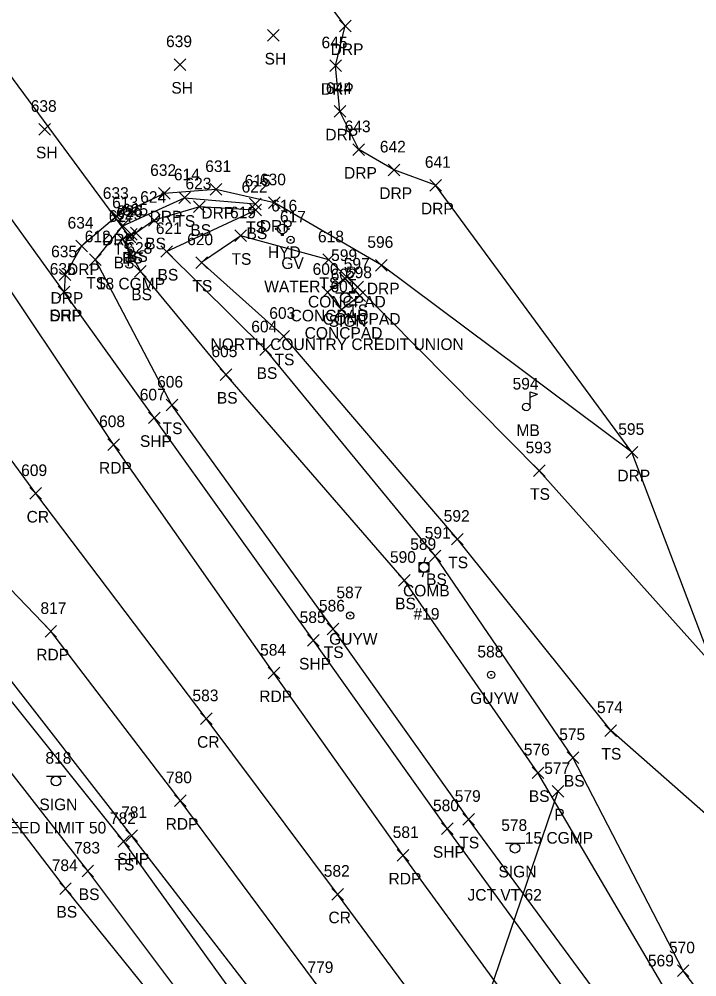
# Model space of a CAD drawing. Extents: x 1623612 to 1625808, y 621345 to 627748.
# Drawn here: x 1625034.6 to 1625151.1, y 625852 to 626016.7 of the extents above; entities that cross this region are included whole.
import ezdxf

# ---------------------------------------------------------------- set-up
doc = ezdxf.new("R2010")
doc.units = 0
for name, color, linetype in [('D_A', 7, 'Continuous'), ('D_C', 7, 'Continuous'), ('D_I', 7, 'Continuous'), ('D_TIC', 7, 'Continuous'), ('DCP', 7, 'Continuous'), ('L_A', 7, 'Continuous'), ('L_I', 7, 'Continuous'), ('L_TIC', 7, 'Continuous'), ('LELB', 7, 'Continuous'), ('LMB', 7, 'Continuous'), ('LS', 7, 'Continuous'), ('LSOGP', 7, 'Continuous'), ('P_A', 7, 'Continuous'), ('P_I', 7, 'Continuous'), ('P_TIC', 7, 'Continuous'), ('PET', 7, 'Continuous'), ('PRC', 7, 'Continuous'), ('PSP', 7, 'Continuous'), ('R_A', 7, 'Continuous'), ('R_I', 7, 'Continuous'), ('R_TIC', 7, 'Continuous'), ('RDP', 7, 'Continuous'), ('S_A', 7, 'Continuous'), ('S_C', 7, 'Continuous'), ('S_I', 7, 'Continuous'), ('SSGN', 7, 'Continuous'), ('U_A', 7, 'Continuous'), ('U_C', 7, 'Continuous'), ('U_I', 7, 'Continuous'), ('UP', 7, 'Continuous'), ('UPGW', 7, 'Continuous'), ('UWFH', 7, 'Continuous'), ('UWV', 7, 'Continuous')]:
    doc.layers.add(name, color=color, linetype=linetype)

msp = doc.modelspace()

# ---------------------------------------------------------------- linework, layer by layer
at = {"layer": 'D_TIC'}
for points in [[(1625052.65, 625978.21), (1625054.65, 625980.21)], [(1625054.65, 625978.21), (1625052.65, 625980.21)], [(1625126.23, 625882.89), (1625128.23, 625884.89)], [(1625128.23, 625882.89), (1625126.23, 625884.89)]]:
    msp.add_lwpolyline(points, dxfattribs=at)
at = {"layer": 'DCP'}
for points in [[(1625053.65, 625979.21), (1625018.74, 626026.52)], [(1625127.23, 625883.89), (1625098.95, 625800.84)]]:
    msp.add_lwpolyline(points, dxfattribs=at)
at = {"layer": 'L_TIC'}
for points in [[(1625077.3, 626012.9), (1625079.3, 626014.9)], [(1625079.3, 626012.9), (1625077.3, 626014.9)], [(1625061.27, 626007.89), (1625063.27, 626009.89)], [(1625063.27, 626007.89), (1625061.27, 626009.89)], [(1625037.99, 625996.76), (1625039.99, 625998.76)], [(1625039.99, 625996.76), (1625037.99, 625998.76)], [(1625062.04, 625984.99), (1625064.04, 625986.99)], [(1625064.04, 625984.99), (1625062.04, 625986.99)], [(1625064.59, 625983.43), (1625066.59, 625985.43)], [(1625066.59, 625983.43), (1625064.59, 625985.43)], [(1625074.2, 625983.93), (1625076.2, 625985.93)], [(1625076.2, 625983.93), (1625074.2, 625985.93)], [(1625074.25, 625982.87), (1625076.25, 625984.87)], [(1625076.25, 625982.87), (1625074.25, 625984.87)], [(1625056.82, 625981.11), (1625058.82, 625983.11)], [(1625058.82, 625981.11), (1625056.82, 625983.11)], [(1625051.42, 625980.17), (1625053.42, 625982.17)], [(1625053.42, 625980.17), (1625051.42, 625982.17)], [(1625051.39, 625977.83), (1625053.39, 625979.83)], [(1625053.39, 625977.83), (1625051.39, 625979.83)], [(1625052.86, 625978.67), (1625054.86, 625980.67)], [(1625054.86, 625978.67), (1625052.86, 625980.67)], [(1625053.71, 625978.94), (1625055.71, 625980.94)], [(1625055.71, 625978.94), (1625053.71, 625980.94)], [(1625071.69, 625978.45), (1625073.69, 625980.45)], [(1625073.69, 625978.45), (1625071.69, 625980.45)], [(1625058.94, 625975.74), (1625060.94, 625977.74)], [(1625060.94, 625975.74), (1625058.94, 625977.74)], [(1625046.71, 625974.33), (1625048.71, 625976.33)], [(1625048.71, 625974.33), (1625046.71, 625976.33)], [(1625064.97, 625973.83), (1625066.97, 625975.83)], [(1625066.97, 625973.83), (1625064.97, 625975.83)], [(1625064.97, 625973.83), (1625066.97, 625975.83)], [(1625066.97, 625973.83), (1625064.97, 625975.83)], [(1625086.81, 625974.31), (1625088.81, 625976.31)], [(1625088.81, 625974.31), (1625086.81, 625976.31)], [(1625054.43, 625972.35), (1625056.43, 625974.35)], [(1625056.43, 625972.35), (1625054.43, 625974.35)], [(1625054.43, 625972.35), (1625056.43, 625974.35)], [(1625056.43, 625972.35), (1625054.43, 625974.35)], [(1625089.6, 625971.11), (1625091.6, 625973.11)], [(1625091.6, 625971.11), (1625089.6, 625973.11)], [(1625091.77, 625969.63), (1625093.77, 625971.63)], [(1625093.77, 625969.63), (1625091.77, 625971.63)], [(1625086.63, 625968.72), (1625088.63, 625970.72)], [(1625088.63, 625968.72), (1625086.63, 625970.72)], [(1625092.15, 625968.15), (1625094.15, 625970.15)], [(1625094.15, 625968.15), (1625092.15, 625970.15)], [(1625092.15, 625968.15), (1625094.15, 625970.15)], [(1625094.15, 625968.15), (1625092.15, 625970.15)], [(1625089.04, 625965.73), (1625091.04, 625967.73)], [(1625091.04, 625965.73), (1625089.04, 625967.73)], [(1625089.04, 625965.73), (1625091.04, 625967.73)], [(1625091.04, 625965.73), (1625089.04, 625967.73)], [(1625079.09, 625961.16), (1625081.09, 625963.16)], [(1625081.09, 625961.16), (1625079.09, 625963.16)], [(1625075.98, 625958.83), (1625077.98, 625960.83)], [(1625077.98, 625958.83), (1625075.98, 625960.83)], [(1625069.14, 625954.57), (1625071.14, 625956.57)], [(1625071.14, 625954.57), (1625069.14, 625956.57)], [(1625059.85, 625949.33), (1625061.85, 625951.33)], [(1625061.85, 625949.33), (1625059.85, 625951.33)], [(1625123.03, 625938.03), (1625125.03, 625940.03)], [(1625125.03, 625938.03), (1625123.03, 625940.03)], [(1625108.95, 625926.26), (1625110.95, 625928.26)], [(1625110.95, 625926.26), (1625108.95, 625928.26)], [(1625105.12, 625923.37), (1625107.12, 625925.37)], [(1625107.12, 625923.37), (1625105.12, 625925.37)], [(1625099.8, 625919.19), (1625101.8, 625921.19)], [(1625101.8, 625919.19), (1625099.8, 625921.19)], [(1625087.56, 625910.82), (1625089.56, 625912.82)], [(1625089.56, 625910.82), (1625087.56, 625912.82)], [(1625135.3, 625893.35), (1625137.3, 625895.35)], [(1625137.3, 625893.35), (1625135.3, 625895.35)], [(1625128.81, 625888.7), (1625130.81, 625890.7)], [(1625130.81, 625888.7), (1625128.81, 625890.7)], [(1625122.78, 625886.07), (1625124.78, 625888.07)], [(1625124.78, 625886.07), (1625122.78, 625888.07)], [(1625110.86, 625878.08), (1625112.86, 625880.08)], [(1625112.86, 625878.08), (1625110.86, 625880.08)], [(1625051.58, 625874.28), (1625053.58, 625876.28)], [(1625053.58, 625874.28), (1625051.58, 625876.28)], [(1625045.4, 625869.19), (1625047.4, 625871.19)], [(1625047.4, 625869.19), (1625045.4, 625871.19)], [(1625041.56, 625866.17), (1625043.56, 625868.17)], [(1625043.56, 625866.17), (1625041.56, 625868.17)], [(1625147.76, 625852.03), (1625149.76, 625854.03)], [(1625149.76, 625852.03), (1625147.76, 625854.03)]]:
    msp.add_lwpolyline(points, dxfattribs=at)
at = {"layer": 'LELB'}
for points in [[(1625193.27, 625769.69), (1625186.11, 625778.21), (1625160.35, 625812.67), (1625137, 625844.95), (1625111.86, 625879.08), (1625088.56, 625911.82), (1625060.85, 625950.33), (1625047.71, 625975.33), (1625052.42, 625981.17), (1625063.04, 625985.99), (1625075.2, 625984.93)], [(1625202.25, 625783.14), (1625192.15, 625794.04), (1625172.86, 625821.27), (1625148.76, 625853.03), (1625129.81, 625889.7), (1625106.12, 625924.37), (1625076.98, 625959.83), (1625059.94, 625976.74), (1625075.25, 625983.87), (1625065.59, 625984.43), (1625057.82, 625982.11), (1625054.71, 625979.94), (1625053.86, 625979.67), (1625052.39, 625978.83), (1625055.43, 625973.35)], [(1625180.7, 625879.29), (1625153.81, 625905.72), (1625124.03, 625939.03), (1625092.77, 625970.63), (1625087.81, 625975.31), (1625072.69, 625979.45), (1625065.97, 625974.83)], [(1625193.27, 625769.69), (1625208.4, 625785.19), (1625203.23, 625794.82), (1625182.56, 625829.07), (1625166.96, 625867.34), (1625136.3, 625894.35), (1625109.95, 625927.26), (1625080.09, 625962.16), (1625065.97, 625974.83)], [(1625202.25, 625783.14), (1625199.96, 625782.54), (1625187.42, 625789.56), (1625167.73, 625817.91), (1625145.11, 625850.78), (1625123.78, 625887.07), (1625100.8, 625920.19), (1625070.14, 625955.57), (1625055.43, 625973.35)], [(1625168.33, 625721.63), (1625149.76, 625746.59), (1625126.59, 625769.43), (1625106.2, 625803.62), (1625076.77, 625841.58), (1625052.58, 625875.28), (1625029.12, 625904.57), (1625004.47, 625931.93), (1624997.4, 625934.09), (1624989.72, 625933.4), (1624984.53, 625931.05), (1624958.97, 625909.04), (1624940.42, 625892.52)], [(1625164.57, 625720.98), (1625144.51, 625741.54), (1625124.06, 625766.95), (1625099.82, 625799.97), (1625096.5, 625807.22), (1625092.35, 625808.68), (1625071.36, 625836.97), (1625046.4, 625870.19), (1625023.79, 625899.18), (1625007.76, 625918.06), (1624995.06, 625928.3), (1624989.75, 625931.76), (1624987.2, 625929.74), (1624981.22, 625924.84), (1624974.29, 625920.07), (1624955.76, 625903.44), (1624945.54, 625893.78)], [(1625164.57, 625720.98), (1625161.19, 625718.67), (1625141.31, 625740.15), (1625121.97, 625765.1), (1625091.91, 625801.43), (1625090.38, 625805.38), (1625068.6, 625834.91), (1625042.56, 625867.17), (1625020.24, 625896.3), (1625004.95, 625914.55), (1624991.81, 625925.45), (1624982.31, 625924.1), (1624975.67, 625918.28), (1624956.23, 625901.03), (1624946.56, 625892.17)]]:
    msp.add_lwpolyline(points, dxfattribs=at)
at = {"layer": 'LMB'}
for p, q in [((1625122.44, 625952.61), (1625123.73, 625952.22)), ((1625122.44, 625950.01), (1625122.44, 625952.61)), ((1625122.44, 625951.71), (1625123.73, 625952.21)), ((1625121.79, 625950), (1625121.79, 625950))]:
    msp.add_line(p, q, dxfattribs=at)
msp.add_circle((1625121.79, 625950), 0.656, dxfattribs=at)
at = {"layer": 'LS'}
for points in [[(1625093.15, 625969.15), (1625090.6, 625972.11), (1625087.63, 625969.72), (1625090.04, 625966.73)], [(1625093.15, 625969.15), (1625090.04, 625966.73)]]:
    msp.add_lwpolyline(points, dxfattribs=at)
at = {"layer": 'LSOGP'}
msp.add_lwpolyline([(1625200.23, 625842.69), (1625180.7, 625879.29), (1625153.81, 625905.72), (1625139.96, 625942.2), (1625106.19, 625988.13), (1625099.02, 625990.77), (1625092.97, 625994.26), (1625089.75, 626000.84), (1625088.99, 626008.69), (1625090.67, 626015.53), (1625069.92, 626043.19), (1625069.59, 626043.56), (1625065.69, 626051.8), (1625058.49, 626067.08), (1625045.18, 626082.05), (1625027.59, 626097.53), (1625025.64, 626131.89)], dxfattribs=at)
at = {"layer": 'P_TIC'}
for points in [[(1625041.32, 625968.75), (1625043.32, 625970.75)], [(1625043.32, 625968.75), (1625041.32, 625970.75)], [(1625056.82, 625947.13), (1625058.82, 625949.13)], [(1625058.82, 625947.13), (1625056.82, 625949.13)], [(1625049.83, 625942.53), (1625051.83, 625944.53)], [(1625051.83, 625942.53), (1625049.83, 625944.53)], [(1625036.44, 625934.12), (1625038.44, 625936.12)], [(1625038.44, 625934.12), (1625036.44, 625936.12)], [(1625039.04, 625910.41), (1625041.04, 625912.41)], [(1625041.04, 625910.41), (1625039.04, 625912.41)], [(1625084.19, 625908.84), (1625086.19, 625910.84)], [(1625086.19, 625908.84), (1625084.19, 625910.84)], [(1625077.39, 625903.23), (1625079.39, 625905.23)], [(1625079.39, 625903.23), (1625077.39, 625905.23)], [(1625065.75, 625895.39), (1625067.75, 625897.39)], [(1625067.75, 625895.39), (1625065.75, 625897.39)], [(1625061.28, 625881.29), (1625063.28, 625883.29)], [(1625063.28, 625881.29), (1625061.28, 625883.29)], [(1625107.2, 625876.47), (1625109.2, 625878.47)], [(1625109.2, 625876.47), (1625107.2, 625878.47)], [(1625052.93, 625875.29), (1625054.93, 625877.29)], [(1625054.93, 625875.29), (1625052.93, 625877.29)], [(1625099.61, 625871.87), (1625101.61, 625873.87)], [(1625101.61, 625871.87), (1625099.61, 625873.87)], [(1625088.34, 625865.2), (1625090.34, 625867.2)], [(1625090.34, 625865.2), (1625088.34, 625867.2)]]:
    msp.add_lwpolyline(points, dxfattribs=at)
at = {"layer": 'PET'}
for points in [[(1625223.77, 625705.98), (1625197.34, 625741.92), (1625177.42, 625768.95), (1625149.4, 625806.39), (1625126.15, 625837.91), (1625100.61, 625872.87), (1625078.39, 625904.23), (1625050.83, 625943.53), (1625026.61, 625979.68), (1625001.56, 626017.54), (1624975.55, 626056.33), (1624956.14, 626085.5), (1624926, 626129.47), (1624907.51, 626155.92), (1624881.56, 626192.36), (1624859.36, 626223.09), (1624835.81, 626254.93), (1624815.05, 626283.37), (1624795.69, 626312.41), (1624789.97, 626324.03), (1624786.26, 626337.17), (1624785.07, 626353.04), (1624787.66, 626371.25), (1624792.4, 626386.87)], [(1625203.84, 625692.06), (1625178.56, 625725.93), (1625159.1, 625752.13), (1625138.75, 625779.51), (1625115.85, 625810.21), (1625086.53, 625849.64), (1625062.28, 625882.29), (1625040.04, 625911.41), (1625011.87, 625940.67), (1624992.38, 625961.15), (1624963.94, 625995.04), (1624945.44, 626018.77), (1624918.36, 626053.4), (1624893.3, 626084.98), (1624858.44, 626129.32)]]:
    msp.add_lwpolyline(points, dxfattribs=at)
at = {"layer": 'PRC'}
msp.add_lwpolyline([(1625213.58, 625698.73), (1625187.25, 625734.61), (1625167.02, 625761.6), (1625139.37, 625799.19), (1625115.73, 625830.47), (1625089.34, 625866.2), (1625066.75, 625896.39), (1625037.44, 625935.12), (1625012.58, 625969.02), (1624983.87, 626006.31), (1624957.44, 626043.36), (1624936.34, 626072.24), (1624905.82, 626116.16), (1624884.45, 626141.57), (1624859.03, 626175.57)], dxfattribs=at)
at = {"layer": 'PSP'}
for points in [[(1625197.89, 625687.83), (1625193.57, 625693.81), (1625173.65, 625722.07), (1625153.52, 625749.21), (1625132.81, 625774.23), (1625108.64, 625805.39), (1625079.11, 625843.61), (1625053.93, 625876.29), (1625030.83, 625905.94), (1625006.8, 625934.64), (1624989.43, 625958.35), (1624960.91, 625992.11), (1624942.41, 626016.35), (1624915.38, 626050.56), (1624890.43, 626082.85), (1624855.5, 626126.62)], [(1625229.23, 625710.23), (1625203.41, 625745.51), (1625190.36, 625762.87), (1625182.48, 625773.25), (1625155.83, 625810.32), (1625133.5, 625842.77), (1625108.2, 625877.47), (1625085.19, 625909.84), (1625057.82, 625948.13), (1625042.32, 625969.75), (1625027.64, 625990.04), (1625006.51, 626020.44), (1624979.39, 626058.85), (1624958.59, 626087.14), (1624930.55, 626127.2)]]:
    msp.add_lwpolyline(points, dxfattribs=at)
at = {"layer": 'R_TIC'}
for points in [[(1625089.67, 626014.53), (1625091.67, 626016.53)], [(1625091.67, 626014.53), (1625089.67, 626016.53)], [(1625087.99, 626007.69), (1625089.99, 626009.69)], [(1625089.99, 626007.69), (1625087.99, 626009.69)], [(1625088.75, 625999.84), (1625090.75, 626001.84)], [(1625090.75, 625999.84), (1625088.75, 626001.84)], [(1625091.97, 625993.26), (1625093.97, 625995.26)], [(1625093.97, 625993.26), (1625091.97, 625995.26)], [(1625098.02, 625989.77), (1625100.02, 625991.77)], [(1625100.02, 625989.77), (1625098.02, 625991.77)], [(1625067.43, 625986.41), (1625069.43, 625988.41)], [(1625069.43, 625986.41), (1625067.43, 625988.41)], [(1625105.19, 625987.13), (1625107.19, 625989.13)], [(1625107.19, 625987.13), (1625105.19, 625989.13)], [(1625058.53, 625985.74), (1625060.53, 625987.74)], [(1625060.53, 625985.74), (1625058.53, 625987.74)], [(1625077.49, 625984.13), (1625079.49, 625986.13)], [(1625079.49, 625984.13), (1625077.49, 625986.13)], [(1625050.38, 625981.79), (1625052.38, 625983.79)], [(1625052.38, 625981.79), (1625050.38, 625983.79)], [(1625044.33, 625976.68), (1625046.33, 625978.68)], [(1625046.33, 625976.68), (1625044.33, 625978.68)], [(1625095.88, 625973.37), (1625097.88, 625975.37)], [(1625097.88, 625973.37), (1625095.88, 625975.37)], [(1625041.5, 625971.75), (1625043.5, 625973.75)], [(1625043.5, 625971.75), (1625041.5, 625973.75)], [(1625041.32, 625968.75), (1625043.32, 625970.75)], [(1625043.32, 625968.75), (1625041.32, 625970.75)], [(1625138.96, 625941.2), (1625140.96, 625943.2)], [(1625140.96, 625941.2), (1625138.96, 625943.2)]]:
    msp.add_lwpolyline(points, dxfattribs=at)
at = {"layer": 'RDP'}
for points in [[(1625106.19, 625988.13), (1625099.02, 625990.77), (1625092.97, 625994.26), (1625089.75, 626000.84), (1625088.99, 626008.69), (1625090.67, 626015.53)], [(1625139.96, 625942.2), (1625096.88, 625974.37), (1625078.49, 625985.13), (1625068.43, 625987.41), (1625059.53, 625986.74), (1625051.38, 625982.79), (1625045.33, 625977.68), (1625042.5, 625972.75), (1625042.32, 625969.75)]]:
    msp.add_lwpolyline(points, dxfattribs=at)
at = {"layer": 'SSGN'}
for p, q in [((1625089.03, 625969.65), (1625092.36, 625969.65)), ((1625090.67, 625968.81), (1625090.67, 625968.81)), ((1625039.28, 625886.49), (1625042.61, 625886.49)), ((1625040.93, 625885.66), (1625040.93, 625885.66)), ((1625118.21, 625874.95), (1625121.55, 625874.95)), ((1625119.86, 625874.11), (1625119.86, 625874.11))]:
    msp.add_line(p, q, dxfattribs=at)
for centre in [(1625090.67, 625968.81), (1625040.93, 625885.66), (1625119.86, 625874.11)]:
    msp.add_circle(centre, 0.833, dxfattribs=at)
at = {"layer": 'UP'}
for p, q in [((1625104.45, 625924.09), (1625104.2, 625923.26)), ((1625103.37, 625921.59), (1625103.37, 625923.26)), ((1625103.37, 625923.26), (1625105.03, 625923.26)), ((1625104.2, 625922.42), (1625104.2, 625922.42)), ((1625105.03, 625923.26), (1625105.03, 625921.59)), ((1625105.03, 625921.59), (1625103.37, 625921.59)), ((1625103.95, 625920.76), (1625104.2, 625921.59))]:
    msp.add_line(p, q, dxfattribs=at)
msp.add_circle((1625104.2, 625922.42), 0.833, dxfattribs=at)
at = {"layer": 'UPGW'}
for centre, radius in [((1625091.5, 625914.11), 0.625), ((1625091.5, 625914.11), 0.0833), ((1625115.74, 625903.92), 0.625), ((1625115.74, 625903.92), 0.0833)]:
    msp.add_circle(centre, radius, dxfattribs=at)
at = {"layer": 'UWFH'}
msp.add_line((1625079.84, 625980.63), (1625079.84, 625980.63), dxfattribs=at)
for centre, radius in [((1625079.84, 625980.63), 0.833), ((1625078.84, 625980.63), 0.167), ((1625079.84, 625979.63), 0.167), ((1625080.84, 625980.63), 0.167)]:
    msp.add_circle(centre, radius, dxfattribs=at)
at = {"layer": 'UWV'}
for radius in [0.625, 0.0833]:
    msp.add_circle((1625081.27, 625978.73), radius, dxfattribs=at)

# ---------------------------------------------------------------- texts
at = {"layer": 'D_A'}
for p in [(1625053.03, 625974.21), (1625126.61, 625878.89)]:
    msp.add_text('P', height=2, dxfattribs=at).set_placement(p)
at = {"layer": 'D_C'}
for s, p in [('18 CGMP', (1625047.94, 625970.21)), ('15 CGMP', (1625121.53, 625874.89))]:
    msp.add_text(s, height=2, dxfattribs=at).set_placement(p)
at = {"layer": 'D_I'}
for s, p in [('629', (1625051.23, 625982.21)), ('577', (1625124.87, 625886.89))]:
    msp.add_text(s, height=2, dxfattribs=at).set_placement(p)
at = {"layer": 'L_A'}
for s, p in [('SH', (1625076.79, 626008.9)), ('SH', (1625060.76, 626003.89)), ('SH', (1625037.48, 625992.76)), ('TS', (1625061.45, 625980.99)), ('BS', (1625064.03, 625979.43)), ('TS', (1625073.61, 625979.93)), ('BS', (1625073.69, 625978.87)), ('TS', (1625050.83, 625976.17)), ('BS', (1625056.26, 625977.11)), ('BS', (1625052.3, 625974.67)), ('BS', (1625053.15, 625974.94)), ('TS', (1625071.1, 625974.45)), ('BS', (1625050.84, 625973.83)), ('BS', (1625058.38, 625971.74)), ('TS', (1625046.12, 625970.33)), ('TS', (1625064.38, 625969.83)), ('TS', (1625064.38, 625969.83)), ('TS', (1625086.22, 625970.31)), ('BS', (1625053.87, 625968.35)), ('BS', (1625053.87, 625968.35)), ('CONCPAD', (1625084.25, 625967.11)), ('CONCPAD', (1625081.27, 625964.72)), ('TS', (1625091.18, 625965.63)), ('CONCPAD', (1625086.79, 625964.15)), ('CONCPAD', (1625086.79, 625964.15)), ('CONCPAD', (1625083.68, 625961.73)), ('CONCPAD', (1625083.68, 625961.73)), ('TS', (1625078.5, 625957.16)), ('BS', (1625075.42, 625954.83)), ('BS', (1625068.58, 625950.57)), ('TS', (1625059.26, 625945.33)), ('MB', (1625120.1, 625945)), ('TS', (1625122.44, 625934.03)), ('TS', (1625108.36, 625922.26)), ('BS', (1625104.56, 625919.37)), ('BS', (1625099.24, 625915.19)), ('TS', (1625086.97, 625906.82)), ('TS', (1625134.71, 625889.35)), ('BS', (1625128.25, 625884.7)), ('BS', (1625122.22, 625882.07)), ('TS', (1625110.27, 625874.08)), ('TS', (1625050.98, 625870.28)), ('BS', (1625044.84, 625865.19)), ('BS', (1625041, 625862.17))]:
    msp.add_text(s, height=2, dxfattribs=at).set_placement(p)
at = {"layer": 'L_I'}
for s, p in [('639', (1625059.85, 626011.89)), ('638', (1625036.58, 626000.76)), ('614', (1625061.2, 625988.99)), ('615', (1625073.36, 625987.93)), ('623', (1625063.18, 625987.43)), ('622', (1625072.84, 625986.87)), ('624', (1625055.41, 625985.11)), ('613', (1625050.58, 625984.17)), ('626', (1625051.39, 625982.67)), ('625', (1625052.3, 625982.94)), ('627', (1625049.99, 625981.83)), ('619', (1625070.84, 625982.45)), ('621', (1625058.1, 625979.74)), ('612', (1625045.87, 625978.33)), ('620', (1625063.48, 625977.83)), ('620', (1625063.48, 625977.83)), ('618', (1625085.97, 625978.31)), ('628', (1625053.02, 625976.35)), ('628', (1625053.02, 625976.35)), ('599', (1625088.23, 625975.11)), ('600', (1625085.05, 625972.72)), ('597', (1625090.4, 625973.63)), ('598', (1625090.79, 625972.15)), ('598', (1625090.79, 625972.15)), ('601', (1625088.12, 625969.73)), ('601', (1625088.12, 625969.73)), ('603', (1625077.6, 625965.16)), ('604', (1625074.5, 625962.83)), ('605', (1625067.65, 625958.57)), ('606', (1625058.31, 625953.33)), ('594', (1625119.43, 625953)), ('593', (1625121.67, 625942.03)), ('592', (1625107.59, 625930.26)), ('591', (1625104.33, 625927.37)), ('590', (1625098.35, 625923.19)), ('586', (1625086.14, 625914.82)), ('574', (1625133.94, 625897.35)), ('575', (1625127.45, 625892.7)), ('576', (1625121.36, 625890.07)), ('579', (1625109.49, 625882.08)), ('782', (1625050.21, 625878.28)), ('783', (1625044.03, 625873.19)), ('784', (1625040.2, 625870.17)), ('570', (1625146.32, 625856.03)), ('569', (1625142.7, 625853.78))]:
    msp.add_text(s, height=2, dxfattribs=at).set_placement(p)
at = {"layer": 'P_A'}
for s, p in [('SHP', (1625039.85, 625964.75)), ('SHP', (1625055.36, 625943.13)), ('RDP', (1625048.32, 625938.53)), ('CR', (1625035.87, 625930.12)), ('RDP', (1625037.53, 625906.41)), ('SHP', (1625082.72, 625904.84)), ('RDP', (1625075.87, 625899.23)), ('CR', (1625065.18, 625891.39)), ('RDP', (1625059.77, 625877.29)), ('SHP', (1625105.73, 625872.47)), ('SHP', (1625051.46, 625871.29)), ('RDP', (1625098.1, 625867.87)), ('CR', (1625087.77, 625861.2))]:
    msp.add_text(s, height=2, dxfattribs=at).set_placement(p)
at = {"layer": 'P_I'}
for s, p in [('636', (1625039.85, 625972.75)), ('607', (1625055.33, 625951.13)), ('608', (1625048.34, 625946.53)), ('609', (1625034.94, 625938.12)), ('817', (1625038.25, 625914.41)), ('585', (1625082.82, 625912.84)), ('584', (1625076.02, 625907.23)), ('583', (1625064.39, 625899.39)), ('780', (1625059.83, 625885.29)), ('781', (1625052.13, 625879.29)), ('580', (1625105.75, 625880.47)), ('581', (1625098.82, 625875.87)), ('582', (1625086.97, 625869.2)), ('779', (1625084.16, 625852.64))]:
    msp.add_text(s, height=2, dxfattribs=at).set_placement(p)
at = {"layer": 'R_A'}
for p in [(1625088.15, 626010.53), (1625086.47, 626003.69), (1625087.24, 625995.84), (1625090.45, 625989.26), (1625096.51, 625985.77), (1625103.68, 625983.13), (1625057.02, 625981.74), (1625065.92, 625982.41), (1625075.98, 625980.13), (1625048.86, 625977.79), (1625042.82, 625972.68), (1625094.37, 625969.37), (1625039.98, 625967.75), (1625039.81, 625964.75), (1625137.45, 625937.2)]:
    msp.add_text('DRP', height=2, dxfattribs=at).set_placement(p)
at = {"layer": 'R_I'}
for s, p in [('645', (1625086.58, 626011.69)), ('644', (1625087.34, 626003.84)), ('643', (1625090.56, 625997.26)), ('642', (1625096.61, 625993.77)), ('641', (1625104.35, 625991.13)), ('632', (1625057.12, 625989.74)), ('631', (1625066.59, 625990.41)), ('630', (1625075.99, 625988.13)), ('633', (1625048.97, 625985.79)), ('634', (1625042.92, 625980.68)), ('596', (1625094.46, 625977.37)), ('635', (1625040.09, 625975.75)), ('636', (1625039.85, 625972.75)), ('595', (1625137.6, 625945.2))]:
    msp.add_text(s, height=2, dxfattribs=at).set_placement(p)
at = {"layer": 'S_A'}
for p in [(1625087.81, 625963.79), (1625038.07, 625880.64), (1625117, 625869.09)]:
    msp.add_text('SIGN', height=2, dxfattribs=at).set_placement(p)
at = {"layer": 'S_C'}
for s, p in [('NORTH COUNTRY CREDIT UNION', (1625067.5, 625959.79)), ('SPEED LIMIT 50', (1625029.2, 625876.64)), ('JCT VT 62', (1625111.68, 625865.09))]:
    msp.add_text(s, height=2, dxfattribs=at).set_placement(p)
at = {"layer": 'S_I'}
for s, p in [('602', (1625088.16, 625971.79)), ('818', (1625039.11, 625888.64)), ('578', (1625117.48, 625877.09))]:
    msp.add_text(s, height=2, dxfattribs=at).set_placement(p)
at = {"layer": 'U_A'}
for s, p in [('HYD', (1625077.36, 625975.63)), ('GV', (1625079.67, 625973.73)), ('COMB', (1625100.59, 625917.42)), ('GUYW', (1625087.89, 625909.11)), ('GUYW', (1625112.13, 625898.92))]:
    msp.add_text(s, height=2, dxfattribs=at).set_placement(p)
at = {"layer": 'U_C'}
for s, p in [('WATER', (1625076.73, 625969.73)), ('#19', (1625102.4, 625913.42))]:
    msp.add_text(s, height=2, dxfattribs=at).set_placement(p)
at = {"layer": 'U_I'}
for s, p in [('616', (1625077.94, 625983.63)), ('617', (1625079.43, 625981.73)), ('589', (1625101.83, 625925.42)), ('587', (1625089.14, 625917.11)), ('588', (1625113.38, 625906.92))]:
    msp.add_text(s, height=2, dxfattribs=at).set_placement(p)

doc.saveas('drawing.dxf')
